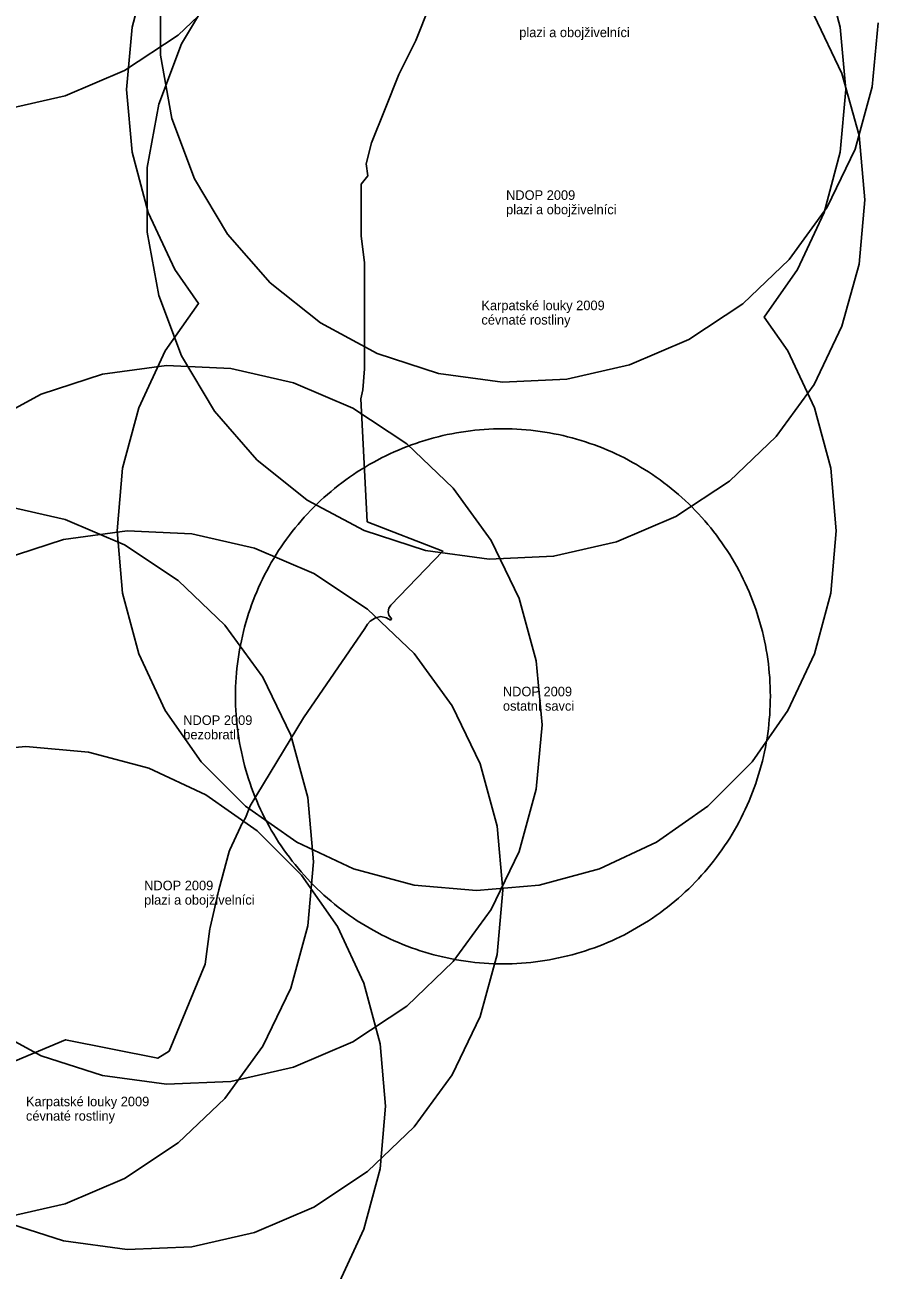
# Model space of a CAD drawing. Extents: x -477403 to -465463, y -1159182 to -1149227.
# Drawn here: x -468146.2 to -467968.2, y -1152216.2 to -1151956.5 of the extents above; entities that cross this region are included whole.
import ezdxf

# ---------------------------------------------------------------- set-up
doc = ezdxf.new("R2010")
doc.units = 0
for name, color, linetype in [('Vrstva 1', 7, 'Continuous'), ('Vrstva 10_stav', 7, 'Continuous'), ('Vrstva 2', 7, 'Continuous')]:
    doc.layers.add(name, color=color, linetype=linetype)

msp = doc.modelspace()

# ---------------------------------------------------------------- linework, layer by layer
at = {"layer": 'Vrstva 10_stav'}
for points in [[(-467979.523, -1151944.348), (-467976.139, -1151956.976), (-467975, -1151970), (-467976.139, -1151983.024), (-467979.523, -1151995.652), (-467985.048, -1152007.5), (-467992, -1152017.428), (-467987.048, -1152024.5), (-467981.523, -1152036.348), (-467978.139, -1152048.976), (-467977, -1152062), (-467978.139, -1152075.024), (-467981.523, -1152087.652), (-467987.048, -1152099.5), (-467994.547, -1152110.209), (-468003.791, -1152119.453), (-468014.5, -1152126.952), (-468026.348, -1152132.477), (-468038.976, -1152135.861), (-468052, -1152137), (-468065.024, -1152135.861), (-468077.652, -1152132.477), (-468089.5, -1152126.952), (-468100.209, -1152119.453), (-468109.453, -1152110.209), (-468116.952, -1152099.5), (-468122.477, -1152087.652), (-468125.861, -1152075.024), (-468127, -1152062), (-468125.861, -1152048.976), (-468122.477, -1152036.348), (-468116.952, -1152024.5), (-468110, -1152014.572), (-468114.952, -1152007.5), (-468120.477, -1151995.652), (-468123.861, -1151983.024), (-468125, -1151970), (-468123.861, -1151956.976), (-468120.477, -1151944.348)], [(-467981.616, -1151954.533), (-467975.782, -1151966.647), (-467972.205, -1151979.608), (-467971, -1151993), (-467972.205, -1152006.392), (-467975.782, -1152019.353), (-467981.616, -1152031.467), (-467989.52, -1152042.345), (-467999.238, -1152051.637), (-468010.46, -1152059.045), (-468022.824, -1152064.329), (-468035.933, -1152067.321), (-468049.365, -1152067.924), (-468062.689, -1152066.12), (-468075.477, -1152061.965), (-468087.317, -1152055.593), (-468097.83, -1152047.21), (-468106.676, -1152037.084), (-468113.573, -1152025.541), (-468118.297, -1152012.953), (-468120.698, -1151999.723), (-468120.698, -1151986.277), (-468118.297, -1151973.047), (-468113.573, -1151960.459), (-468106.676, -1151948.916)], [(-468104.52, -1151949.345), (-468114.238, -1151958.637), (-468125.46, -1151966.045), (-468137.824, -1151971.329), (-468150.933, -1151974.321), (-468164.365, -1151974.924), (-468177.689, -1151973.12), (-468190.477, -1151968.965), (-468202.317, -1151962.593), (-468212.83, -1151954.21)], [(-467968.25, -1151956.07), (-467969.455, -1151969.462), (-467973.032, -1151982.423), (-467978.866, -1151994.537), (-467986.77, -1152005.415), (-467996.488, -1152014.707), (-468007.71, -1152022.115), (-468020.074, -1152027.399), (-468033.183, -1152030.391), (-468046.615, -1152030.994), (-468059.939, -1152029.19), (-468072.727, -1152025.035), (-468084.567, -1152018.663), (-468095.08, -1152010.28), (-468103.926, -1152000.154), (-468110.823, -1151988.611), (-468115.547, -1151976.023), (-468117.948, -1151962.793), (-468117.948, -1151949.347)], [(-468061.812, -1151952.625), (-468064.656, -1151959.75), (-468068.25, -1151966.875), (-468071.094, -1151974), (-468073.938, -1151981.125), (-468075.031, -1151985.5), (-468074.656, -1151988), (-468076.094, -1151989.75), (-468076.094, -1151994.75), (-468076.094, -1152000.5), (-468075.375, -1152006.125), (-468075.375, -1152011.875), (-468075.375, -1152017.625), (-468075.375, -1152022.625), (-468075.375, -1152028.25), (-468075.719, -1152032.625)], [(-468061.812, -1151952.625), (-468064.656, -1151959.75), (-468068.25, -1151966.875), (-468071.094, -1151974), (-468073.938, -1151981.125), (-468075.031, -1151985.5), (-468074.656, -1151988), (-468076.094, -1151989.75), (-468076.094, -1151994.75), (-468076.094, -1152000.5), (-468075.375, -1152006.125), (-468075.375, -1152011.875), (-468075.375, -1152017.625), (-468075.375, -1152022.625), (-468075.375, -1152028.25), (-468075.719, -1152032.625)], [(-468154.657, -1152039.897), (-468142.817, -1152033.525), (-468130.029, -1152029.37), (-468116.705, -1152027.566), (-468103.273, -1152028.169), (-468090.164, -1152031.161), (-468077.8, -1152036.445), (-468066.578, -1152043.853), (-468056.86, -1152053.145), (-468048.956, -1152064.023), (-468043.122, -1152076.137), (-468039.545, -1152089.098), (-468038.34, -1152102.49), (-468039.545, -1152115.882), (-468043.122, -1152128.843), (-468048.956, -1152140.957), (-468056.86, -1152151.835), (-468066.578, -1152161.127), (-468077.8, -1152168.535), (-468090.164, -1152173.819), (-468103.273, -1152176.811), (-468116.705, -1152177.414), (-468130.029, -1152175.61), (-468142.817, -1152171.455), (-468154.657, -1152165.083)], [(-468075.719, -1152032.625), (-468076.125, -1152034.5), (-468074.812, -1152060.125), (-468059.031, -1152066.25), (-468069.875, -1152077.5), (-468070.281, -1152078.125), (-468070.438, -1152078.875), (-468070.281, -1152079.625), (-468069.75, -1152080.375), (-468069.969, -1152080.625), (-468070.812, -1152080.125), (-468071.969, -1152079.875), (-468073.094, -1152080.125), (-468074.188, -1152080.875), (-468074.75, -1152081.5), (-468075.312, -1152082.375), (-468088.094, -1152101), (-468099.219, -1152119.375), (-468099.469, -1152119.875), (-468100.219, -1152121.875), (-468101.156, -1152123.5), (-468101.281, -1152123.75), (-468103.5, -1152128.5), (-468103.594, -1152128.875), (-468105.781, -1152136.875), (-468107.562, -1152144.75), (-468107.625, -1152145), (-468108.625, -1152152.375), (-468116.156, -1152170.5), (-468118.5, -1152172), (-468137.75, -1152168.125), (-468162.156, -1152178.375)], [(-468075.719, -1152032.625), (-468076.125, -1152034.5), (-468074.812, -1152060.125), (-468059.031, -1152066.25), (-468069.875, -1152077.5), (-468070.281, -1152078.125), (-468070.438, -1152078.875), (-468070.281, -1152079.625), (-468069.75, -1152080.375), (-468069.969, -1152080.625), (-468070.812, -1152080.125), (-468071.969, -1152079.875), (-468073.094, -1152080.125), (-468074.188, -1152080.875), (-468074.75, -1152081.5), (-468075.312, -1152082.375), (-468088.094, -1152101), (-468099.219, -1152119.375), (-468099.469, -1152119.875), (-468100.219, -1152121.875), (-468101.156, -1152123.5), (-468101.281, -1152123.75), (-468103.5, -1152128.5), (-468103.594, -1152128.875), (-468105.781, -1152136.875), (-468107.562, -1152144.75), (-468107.625, -1152145), (-468108.625, -1152152.375), (-468116.156, -1152170.5), (-468118.5, -1152172), (-468137.75, -1152168.125), (-468162.156, -1152178.375)], [(-468098.927, -1152077.437), (-468098.586, -1152076.525), (-468098.229, -1152075.619), (-468097.857, -1152074.72), (-468097.468, -1152073.827), (-468097.065, -1152072.941), (-468096.645, -1152072.062), (-468096.211, -1152071.191), (-468095.762, -1152070.327), (-468095.297, -1152069.472), (-468094.818, -1152068.625), (-468094.323, -1152067.786), (-468093.815, -1152066.956), (-468093.292, -1152066.134), (-468092.754, -1152065.323), (-468092.203, -1152064.52), (-468091.638, -1152063.728), (-468091.058, -1152062.945), (-468090.466, -1152062.173), (-468089.86, -1152061.411), (-468089.24, -1152060.66), (-468088.608, -1152059.919), (-468087.963, -1152059.19), (-468087.305, -1152058.472), (-468086.635, -1152057.766), (-468085.953, -1152057.072), (-468085.258, -1152056.389), (-468084.552, -1152055.719), (-468083.834, -1152055.061), (-468083.105, -1152054.416), (-468082.365, -1152053.784), (-468081.614, -1152053.165), (-468080.852, -1152052.559), (-468080.079, -1152051.966), (-468079.297, -1152051.387), (-468078.504, -1152050.822), (-468077.702, -1152050.27), (-468076.89, -1152049.733), (-468076.069, -1152049.21), (-468075.239, -1152048.701), (-468074.4, -1152048.207), (-468073.553, -1152047.727), (-468072.697, -1152047.263), (-468071.833, -1152046.813), (-468070.962, -1152046.379), (-468070.083, -1152045.96), (-468069.197, -1152045.556), (-468068.305, -1152045.168), (-468067.405, -1152044.795), (-468066.499, -1152044.438), (-468065.587, -1152044.098), (-468064.67, -1152043.773), (-468063.746, -1152043.464), (-468062.818, -1152043.171), (-468061.884, -1152042.894), (-468060.946, -1152042.634), (-468060.004, -1152042.39), (-468059.057, -1152042.163), (-468058.107, -1152041.952), (-468057.153, -1152041.758), (-468056.195, -1152041.581), (-468055.235, -1152041.42), (-468054.272, -1152041.276), (-468053.307, -1152041.149), (-468052.34, -1152041.039), (-468051.371, -1152040.946), (-468050.4, -1152040.869), (-468049.428, -1152040.81), (-468048.456, -1152040.767), (-468047.482, -1152040.742), (-468046.509, -1152040.733), (-468045.535, -1152040.742), (-468044.562, -1152040.767), (-468043.589, -1152040.81), (-468042.618, -1152040.869), (-468041.647, -1152040.946), (-468040.678, -1152041.039), (-468039.711, -1152041.149), (-468038.745, -1152041.276), (-468037.783, -1152041.42), (-468036.822, -1152041.581), (-468035.865, -1152041.758), (-468034.911, -1152041.952), (-468033.961, -1152042.163), (-468033.014, -1152042.39), (-468032.071, -1152042.634), (-468031.133, -1152042.894), (-468030.2, -1152043.171), (-468029.271, -1152043.464), (-468028.348, -1152043.773), (-468027.43, -1152044.098), (-468026.518, -1152044.438), (-468025.612, -1152044.795), (-468024.713, -1152045.168), (-468023.82, -1152045.556), (-468022.934, -1152045.96), (-468022.056, -1152046.379), (-468021.184, -1152046.813), (-468020.321, -1152047.263), (-468019.465, -1152047.727), (-468018.618, -1152048.207)], [(-468018.618, -1152048.207), (-468017.779, -1152048.701), (-468016.949, -1152049.21), (-468016.128, -1152049.733), (-468015.316, -1152050.27), (-468014.514, -1152050.822), (-468013.721, -1152051.387), (-468012.938, -1152051.966), (-468012.166, -1152052.559), (-468011.404, -1152053.165), (-468010.653, -1152053.784), (-468009.912, -1152054.416), (-468009.183, -1152055.061), (-468008.466, -1152055.719), (-468007.759, -1152056.389), (-468007.065, -1152057.072), (-468006.383, -1152057.766), (-468005.712, -1152058.472), (-468005.055, -1152059.19), (-468004.41, -1152059.919), (-468003.777, -1152060.66), (-468003.158, -1152061.411), (-468002.552, -1152062.173), (-468001.959, -1152062.945), (-468001.38, -1152063.728), (-468000.815, -1152064.52), (-468000.263, -1152065.323), (-467999.726, -1152066.134), (-467999.203, -1152066.956), (-467998.694, -1152067.786), (-467998.2, -1152068.625), (-467997.721, -1152069.472), (-467997.256, -1152070.327), (-467996.807, -1152071.191), (-467996.372, -1152072.062), (-467995.953, -1152072.941), (-467995.549, -1152073.827), (-467995.161, -1152074.72), (-467994.789, -1152075.619), (-467994.432, -1152076.525), (-467994.091, -1152077.437), (-467993.766, -1152078.355), (-467993.457, -1152079.278), (-467993.164, -1152080.206), (-467992.888, -1152081.14), (-467992.627, -1152082.078), (-467992.384, -1152083.021), (-467992.156, -1152083.967), (-467991.946, -1152084.918), (-467991.752, -1152085.872), (-467991.574, -1152086.829), (-467991.413, -1152087.789), (-467991.27, -1152088.752), (-467991.142, -1152089.717), (-467991.032, -1152090.685), (-467990.939, -1152091.654), (-467990.863, -1152092.624), (-467990.803, -1152093.596), (-467990.761, -1152094.569), (-467990.735, -1152095.542), (-467990.727, -1152096.516)], [(-468150.933, -1152056.679), (-468137.824, -1152059.671), (-468125.46, -1152064.955), (-468114.238, -1152072.363), (-468104.52, -1152081.655), (-468096.616, -1152092.533), (-468090.782, -1152104.647), (-468087.205, -1152117.608), (-468086, -1152131), (-468087.205, -1152144.392), (-468090.782, -1152157.353), (-468096.616, -1152169.467), (-468104.52, -1152180.345), (-468114.238, -1152189.637), (-468125.46, -1152197.045), (-468137.824, -1152202.329), (-468150.933, -1152205.321)], [(-468150.977, -1152067.995), (-468138.189, -1152063.84), (-468124.865, -1152062.036), (-468111.433, -1152062.639), (-468098.324, -1152065.631), (-468085.96, -1152070.915), (-468074.738, -1152078.323), (-468065.02, -1152087.615), (-468057.116, -1152098.493), (-468051.282, -1152110.607), (-468047.705, -1152123.568), (-468046.5, -1152136.96), (-468047.705, -1152150.352), (-468051.282, -1152163.313), (-468057.116, -1152175.427), (-468065.02, -1152186.305), (-468074.738, -1152195.597), (-468085.96, -1152203.005), (-468098.324, -1152208.289), (-468111.433, -1152211.281), (-468124.865, -1152211.884), (-468138.189, -1152210.08), (-468150.977, -1152205.925)], [(-468056.195, -1152151.45), (-468057.153, -1152151.273), (-468058.107, -1152151.079), (-468059.057, -1152150.868), (-468060.004, -1152150.641), (-468060.946, -1152150.397), (-468061.884, -1152150.137), (-468062.818, -1152149.86), (-468063.746, -1152149.568), (-468064.67, -1152149.259), (-468065.587, -1152148.934), (-468066.499, -1152148.593), (-468067.405, -1152148.236), (-468068.305, -1152147.863), (-468069.197, -1152147.475), (-468070.083, -1152147.071), (-468070.962, -1152146.652), (-468071.833, -1152146.218), (-468072.697, -1152145.768), (-468073.553, -1152145.304), (-468074.4, -1152144.824), (-468075.239, -1152144.33), (-468076.069, -1152143.822), (-468076.89, -1152143.298), (-468077.702, -1152142.761), (-468078.504, -1152142.21), (-468079.297, -1152141.644), (-468080.079, -1152141.065), (-468080.852, -1152140.473), (-468081.614, -1152139.866), (-468082.365, -1152139.247), (-468083.105, -1152138.615), (-468083.834, -1152137.97), (-468084.552, -1152137.312), (-468085.258, -1152136.642), (-468085.953, -1152135.96), (-468086.635, -1152135.265), (-468087.305, -1152134.559), (-468087.963, -1152133.841), (-468088.608, -1152133.112), (-468089.24, -1152132.372), (-468089.86, -1152131.62), (-468090.466, -1152130.859), (-468091.058, -1152130.086), (-468091.638, -1152129.304), (-468092.203, -1152128.511), (-468092.754, -1152127.709), (-468093.292, -1152126.897), (-468093.815, -1152126.076), (-468094.323, -1152125.246), (-468094.818, -1152124.407), (-468095.297, -1152123.559), (-468095.762, -1152122.704), (-468096.211, -1152121.84), (-468096.645, -1152120.969), (-468097.065, -1152120.09), (-468097.468, -1152119.204), (-468097.857, -1152118.311), (-468098.229, -1152117.412), (-468098.586, -1152116.506), (-468098.927, -1152115.594), (-468099.252, -1152114.676), (-468099.561, -1152113.753), (-468099.854, -1152112.825), (-468100.13, -1152111.891), (-468100.39, -1152110.953), (-468100.634, -1152110.011), (-468100.861, -1152109.064), (-468101.072, -1152108.113), (-468101.266, -1152107.159), (-468101.444, -1152106.202), (-468101.604, -1152105.242), (-468101.748, -1152104.279), (-468101.875, -1152103.314), (-468101.985, -1152102.346), (-468102.079, -1152101.377), (-468102.155, -1152100.407), (-468102.215, -1152099.435), (-468102.257, -1152098.462), (-468102.282, -1152097.489), (-468102.291, -1152096.516), (-468102.282, -1152095.542), (-468102.257, -1152094.569), (-468102.215, -1152093.596), (-468102.155, -1152092.624), (-468102.079, -1152091.654), (-468101.985, -1152090.685), (-468101.875, -1152089.717), (-468101.748, -1152088.752), (-468101.604, -1152087.789), (-468101.444, -1152086.829), (-468101.266, -1152085.872), (-468101.072, -1152084.918), (-468100.861, -1152083.967), (-468100.634, -1152083.021), (-468100.39, -1152082.078), (-468100.13, -1152081.14), (-468099.854, -1152080.206), (-468099.561, -1152079.278), (-468099.252, -1152078.355), (-468098.927, -1152077.437)], [(-467990.727, -1152096.516), (-467990.735, -1152097.489), (-467990.761, -1152098.462), (-467990.803, -1152099.435), (-467990.863, -1152100.407), (-467990.939, -1152101.377), (-467991.032, -1152102.346), (-467991.142, -1152103.314), (-467991.27, -1152104.279), (-467991.413, -1152105.242), (-467991.574, -1152106.202), (-467991.752, -1152107.159), (-467991.946, -1152108.113), (-467992.156, -1152109.064), (-467992.384, -1152110.011), (-467992.627, -1152110.953), (-467992.888, -1152111.891), (-467993.164, -1152112.825), (-467993.457, -1152113.753), (-467993.766, -1152114.676), (-467994.091, -1152115.594), (-467994.432, -1152116.506), (-467994.789, -1152117.412), (-467995.161, -1152118.311), (-467995.549, -1152119.204), (-467995.953, -1152120.09), (-467996.372, -1152120.969), (-467996.807, -1152121.84), (-467997.256, -1152122.704), (-467997.721, -1152123.559), (-467998.2, -1152124.407), (-467998.694, -1152125.246), (-467999.203, -1152126.076), (-467999.726, -1152126.897), (-468000.263, -1152127.709), (-468000.815, -1152128.511), (-468001.38, -1152129.304), (-468001.959, -1152130.086), (-468002.552, -1152130.859), (-468003.158, -1152131.62), (-468003.777, -1152132.372), (-468004.41, -1152133.112), (-468005.055, -1152133.841), (-468005.712, -1152134.559), (-468006.383, -1152135.265), (-468007.065, -1152135.96), (-468007.759, -1152136.642), (-468008.466, -1152137.312), (-468009.183, -1152137.97), (-468009.912, -1152138.615), (-468010.653, -1152139.247), (-468011.404, -1152139.866), (-468012.166, -1152140.473), (-468012.938, -1152141.065), (-468013.721, -1152141.644), (-468014.514, -1152142.21), (-468015.316, -1152142.761), (-468016.128, -1152143.298), (-468016.949, -1152143.822), (-468017.779, -1152144.33), (-468018.618, -1152144.824), (-468019.465, -1152145.304), (-468020.321, -1152145.768), (-468021.184, -1152146.218), (-468022.056, -1152146.652), (-468022.934, -1152147.071), (-468023.82, -1152147.475), (-468024.713, -1152147.863), (-468025.612, -1152148.236), (-468026.518, -1152148.593), (-468027.43, -1152148.934), (-468028.348, -1152149.259), (-468029.271, -1152149.568), (-468030.2, -1152149.86), (-468031.133, -1152150.137), (-468032.071, -1152150.397), (-468033.014, -1152150.641), (-468033.961, -1152150.868), (-468034.911, -1152151.079), (-468035.865, -1152151.273), (-468036.822, -1152151.45), (-468037.783, -1152151.611), (-468038.745, -1152151.755), (-468039.711, -1152151.882), (-468040.678, -1152151.992), (-468041.647, -1152152.085), (-468042.618, -1152152.162), (-468043.589, -1152152.221), (-468044.562, -1152152.264), (-468045.535, -1152152.289), (-468046.509, -1152152.298), (-468047.482, -1152152.289), (-468048.456, -1152152.264), (-468049.428, -1152152.221), (-468050.4, -1152152.162), (-468051.371, -1152152.085), (-468052.34, -1152151.992), (-468053.307, -1152151.882), (-468054.272, -1152151.755), (-468055.235, -1152151.611), (-468056.195, -1152151.45)], [(-468159.024, -1152108.139), (-468146, -1152107), (-468132.976, -1152108.139), (-468120.348, -1152111.523), (-468108.5, -1152117.048), (-468097.791, -1152124.547), (-468088.547, -1152133.791), (-468081.048, -1152144.5), (-468075.523, -1152156.348), (-468072.139, -1152168.976), (-468071, -1152182), (-468072.139, -1152195.024), (-468075.523, -1152207.652), (-468081.048, -1152219.5)]]:
    msp.add_lwpolyline(points, dxfattribs=at)

# ---------------------------------------------------------------- texts
at = {"layer": 'Vrstva 1'}
for s, p in [('plazi a obojživelníci', (-468043.099, -1151959.07)), ('plazi a obojživelníci', (-468043.099, -1151959.07)), ('plazi a obojživelníci', (-468045.849, -1151996)), ('plazi a obojživelníci', (-468045.849, -1151996)), ('cévnaté rostliny', (-468051, -1152019)), ('cévnaté rostliny', (-468051, -1152019)), ('ostatní savci', (-468046.509, -1152099.515)), ('ostatní savci', (-468046.509, -1152099.515)), ('bezobratlí', (-468113.189, -1152105.49)), ('bezobratlí', (-468113.189, -1152105.49)), ('plazi a obojživelníci', (-468121.349, -1152139.96)), ('plazi a obojživelníci', (-468121.349, -1152139.96)), ('cévnaté rostliny', (-468146, -1152185)), ('cévnaté rostliny', (-468146, -1152185))]:
    msp.add_text(s, height=2, dxfattribs=at).set_placement(p)
at = {"layer": 'Vrstva 2'}
for s, p in [('NDOP 2009', (-468045.849, -1151993)), ('NDOP 2009', (-468045.849, -1151993)), ('Karpatské louky 2009', (-468051, -1152016)), ('Karpatské louky 2009', (-468051, -1152016)), ('NDOP 2009', (-468046.509, -1152096.515)), ('NDOP 2009', (-468046.509, -1152096.515)), ('NDOP 2009', (-468113.189, -1152102.49)), ('NDOP 2009', (-468113.189, -1152102.49)), ('NDOP 2009', (-468121.349, -1152136.96)), ('NDOP 2009', (-468121.349, -1152136.96)), ('Karpatské louky 2009', (-468146, -1152182)), ('Karpatské louky 2009', (-468146, -1152182))]:
    msp.add_text(s, height=2, dxfattribs=at).set_placement(p)

doc.saveas('drawing.dxf')
